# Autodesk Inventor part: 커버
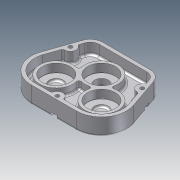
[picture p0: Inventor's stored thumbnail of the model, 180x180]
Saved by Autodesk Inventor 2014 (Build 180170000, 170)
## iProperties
Company: 한국ATC센터
Created: 2014-12
Part Number: 커버
Document SubType Name: Modeling
Designer: KYOUNG IL JANG
Density: 1 g/cm^3
Mass: 160.364 g
Surface Area: 512.085 cm^2
Volume: 160.364 cm^3
Material: 일반
Appearance: 기본값
Author: KYOUNG IL JANG
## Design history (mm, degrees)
sketch "스케치1"
  geometry: L1 (-66.565, -20.803)-(-47, 36); L2 (47, 36)-(66.565, -20.803); L3 (-32.527, -68.527)-(32.527, -68.527); L4 (-47, 36)-(47, 36); C1 r 28 at (0, 0); C2 r 18 at (-32.527, -32.527); C3 r 18 at (32.527, -32.527); A1 r 36 centre (-32.527, -32.527) between (-66.565, -20.803) and (-32.527, -68.527); A2 r 36 centre (32.527, -32.527) between (32.527, -68.527) and (66.565, -20.803); 2 further points
  constraints: 8 end point, 6 tangent, 5 centre point, 4 point on circle, 3 coincident, 2 equal radius, 1 equal length, 1 horizontal alignment, 1 midpoint, 1 vertical alignment
  dimensions: "d0" = 56 diameter of C1; "d1" = 36 diameter of C2; "d2" = 90 deg dimension on point (0, 0) C3.centre C2.centre; "d3" = 36 radius of A1; "d4" = 104.52691 distance between parallel lines of L3 L4 (derived); "d5" = 94 distance of L1.end L2.start; "d65" = 36 distance from line of point (0, 0) L4
extrude "돌출1" new body sketch "스케치1" distance "d6" = 25; taper "d7" = 0 deg
fillet "모깎기1" dims "d8" = 18
feature "쉘1" dims "d9" = 9, "d10" = 5
sketch "스케치2"
  geometry: C1 r 24 at (1.635, -63.527); C2 r 24 at (66.689, -63.527); C3 r 24 at (34.162, -31); 4 further points
  constraints: 4 coincident, 3 centre point, 1 equal radius
  dimensions: "d11" = 48 diameter of C3; "d12" = 48 diameter of C2
extrude "돌출2" join sketch "스케치2" distance "d13" = 11; taper "d14" = 0 deg
hole "구멍1" diameter "d17" = 20; stored, may be unused: countersink angle "d21" = 90 deg, drill point angle "d23" = 0 deg; dims "d15" = 10, "d16" = 10, "d18" = 6, "d19" = 40, "d20" = 12, "d22" = 3
hole "구멍2" diameter "d26" = 20; stored, may be unused: countersink angle "d30" = 90 deg, drill point angle "d32" = 0 deg; dims "d24" = 10, "d25" = 10, "d27" = 6, "d28" = 40, "d29" = 12, "d31" = 3
hole "구멍3" diameter "d35" = 20; stored, may be unused: countersink angle "d39" = 90 deg, drill point angle "d41" = 118 deg; dims "d33" = 10, "d34" = 10, "d36" = 6, "d37" = 40, "d38" = 12, "d40" = 3
sketch "스케치3"
  geometry: C1 r 15 at (0, 0); C2 r 20 at (0, 0); 1 further point
  constraints: 2 centre point, 2 coincident
  dimensions: "d42" = 40 diameter of C2; "d43" = 30 diameter of C1
extrude "돌출3" join sketch "스케치3" distance "d44" = 8; taper "d45" = 0 deg
feature "면 기울기1" dims angle "d46" = 10 deg
fillet "모깎기2" dims "d47" = 3
fillet "모깎기3" dims "d48" = 0.3
fillet "모깎기6" dims "d66" = 0.1
sketch "스케치4"
  geometry: L1 (-61.837, -22.432)-(-46.453, 22.233) reference; L2 (46.453, 22.233)-(61.837, -22.432) reference; L3 (32.527, -63.527)-(-32.527, -63.527) reference; L4 (-34.162, 31)-(34.162, 31) reference; A1 r 8 centre (51.7, 7) between (49.095, 14.564) and (54.305, -0.564); A2 r 8 centre (-51.7, 7) between (-54.305, -0.564) and (-49.095, 14.564); A3 r 8 centre (0, -63.527) between (8, -63.527) and (-8, -63.527)
  constraints: 8 point on line, 6 point on circle, 3 centre point, 2 equal radius, 1 horizontal alignment, 1 midpoint
  dimensions: "d49" = 8 radius of A1; "d51" = 24 distance from line of A2.centre L4
extrude "돌출4" join sketch "스케치4" stored distance "d52" = 8; taper "d53" = 0 deg
fillet "모깎기4" dims "d54" = 3
sketch "스케치5"
  geometry: A1 r 8 centre (-51.7, 7) between (-52.144, -0.988) and (-47.131, 13.567) reference; A2 r 8 centre (0, -63.527) between (7.697, -61.345) and (-7.697, -61.345) reference; A3 r 8 centre (51.7, 7) between (47.131, 13.567) and (52.144, -0.988) reference; 1 further point
hole "구멍4" sketch "스케치5" at (0, -63.527), (-51.7, 7), (51.7, 7) diameter "d55" = 5.5; stored, may be unused: countersink angle "d59" = 90 deg, drill point angle "d61" = 118 deg; dims "d56" = 6, "d57" = 9.5, "d58" = 5.4, "d60" = 3
sketch "스케치6"
  geometry: L1 (-51.181, 23.862)-(-66.565, -20.803) reference; L2 (66.565, -20.803)-(51.181, 23.862) reference; L3 (-32.527, -68.527)-(32.527, -68.527) reference; L4 (-50.153, 11.491)-(-54.881, 13.119); L5 (-53.247, 2.509)-(-57.974, 4.137); L6 (50.153, 11.491)-(54.881, 13.119); L7 (53.247, 2.509)-(57.974, 4.137); L8 (4.75, -63.527)-(4.75, -68.527); L9 (-4.75, -63.527)-(-4.75, -68.527); A1 r 4.75 centre (-51.7, 7) between (-54.994, 3.578) and (-52.188, 11.725) reference; A2 r 4.75 centre (51.7, 7) between (52.188, 11.725) and (54.994, 3.578) reference; A3 r 4.75 centre (0, -63.527) between (4.308, -65.527) and (-4.308, -65.527) reference; 1 further point
  constraints: 12 end point, 6 perpendicular, 6 point on circle, 6 point on line, 6 tangent
extrude "돌출5" cut sketch "스케치6" distance "d62" = 5.4; taper "d63" = 0 deg
fillet "모깎기5" dims "d64" = 3
node "솔리드1"
